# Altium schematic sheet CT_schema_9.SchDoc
size 278 x 170 mm
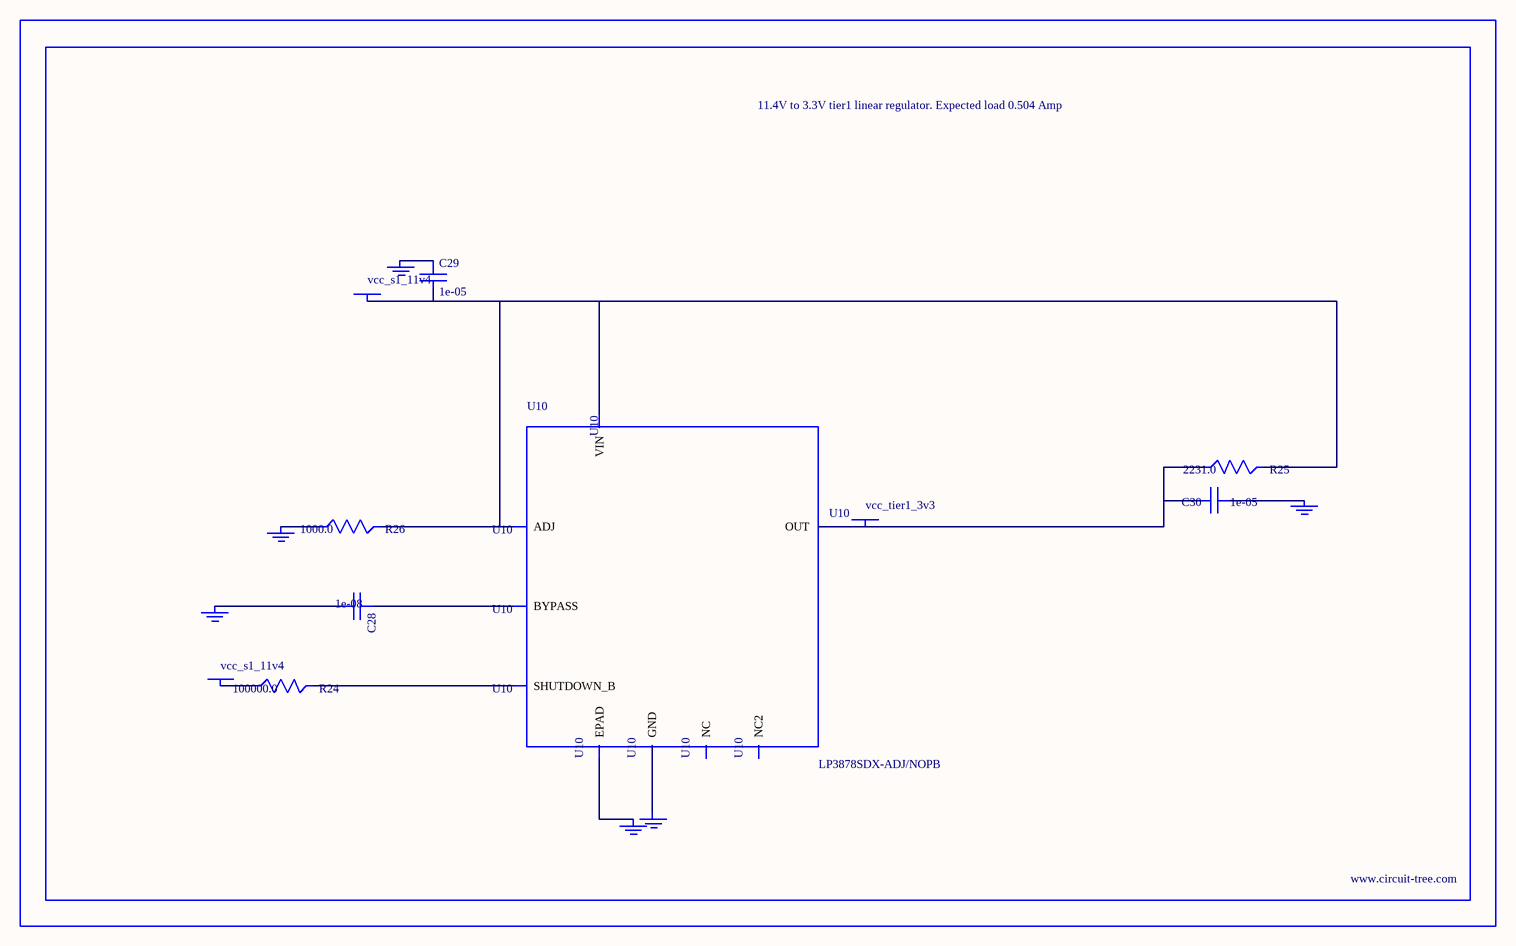
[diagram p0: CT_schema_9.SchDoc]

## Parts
BORDER8  (no value)
C28  1e-08  [C0402]
C29  1e-05  [C1210]
C30  1e-05  [C1210]
GND_INSTANCE_8_0  (no value)
GND_INSTANCE_8_1  (no value)
GND_INSTANCE_8_2  (no value)
GND_INSTANCE_8_3  (no value)
GND_INSTANCE_8_4  (no value)
GND_INSTANCE_8_5  (no value)
POWER_INSTANCE_8_0  vcc_s1_11v4
POWER_INSTANCE_8_1  vcc_s1_11v4
POWER_INSTANCE_8_2  vcc_tier1_3v3
R24  100000.0  [R0603]
R25  2231.0  [R0603]
R26  1000.0  [R0603]
U10  LP3878SDX-ADJ/NOPB  [WSON-8]

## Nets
NetC28_1: C28.1 U10.1(BYPASS)
NetC28_2: C28.2 GND_INSTANCE_8_0.0(GND)
NetC29_1: C29.1 GND_INSTANCE_8_1.0(GND)
NetC29_2: C29.2 POWER_INSTANCE_8_0.0(PWR) R25.2 R26.2 U10.4(VIN) U10.6(ADJ)
NetC30_1: C30.1 GND_INSTANCE_8_2.0(GND)
NetC30_2: C30.2 POWER_INSTANCE_8_2.0(PWR) R25.1 U10.5(OUT)
NetGND_INSTANCE_8_3_0: GND_INSTANCE_8_3.0(GND) R26.1
NetGND_INSTANCE_8_4_0: GND_INSTANCE_8_4.0(GND) U10.PAD(EPAD)
NetGND_INSTANCE_8_5_0: GND_INSTANCE_8_5.0(GND) U10.3(GND)
NetPOWER_INSTANCE_8_1_0: POWER_INSTANCE_8_1.0(PWR) R24.1
NetR24_2: R24.2 U10.8(SHUTDOWN_B)

Not connected (* = marked no-connect by the designer): U10 2(NC) 7(NC2)

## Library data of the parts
BORDER8 = BORDER_PAGE8
C28 = C0402C103K3RAC
C29 = C1210C106K5PACTU
C30 = GRM32DR61E106MA12L
GND_INSTANCE_8_0-GND_INSTANCE_8_5 = GND
POWER_INSTANCE_8_0-POWER_INSTANCE_8_2 = PWR
R24 = RC0603JR-07100KL
R25 = R25
R26 = RC0603JR-071KL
